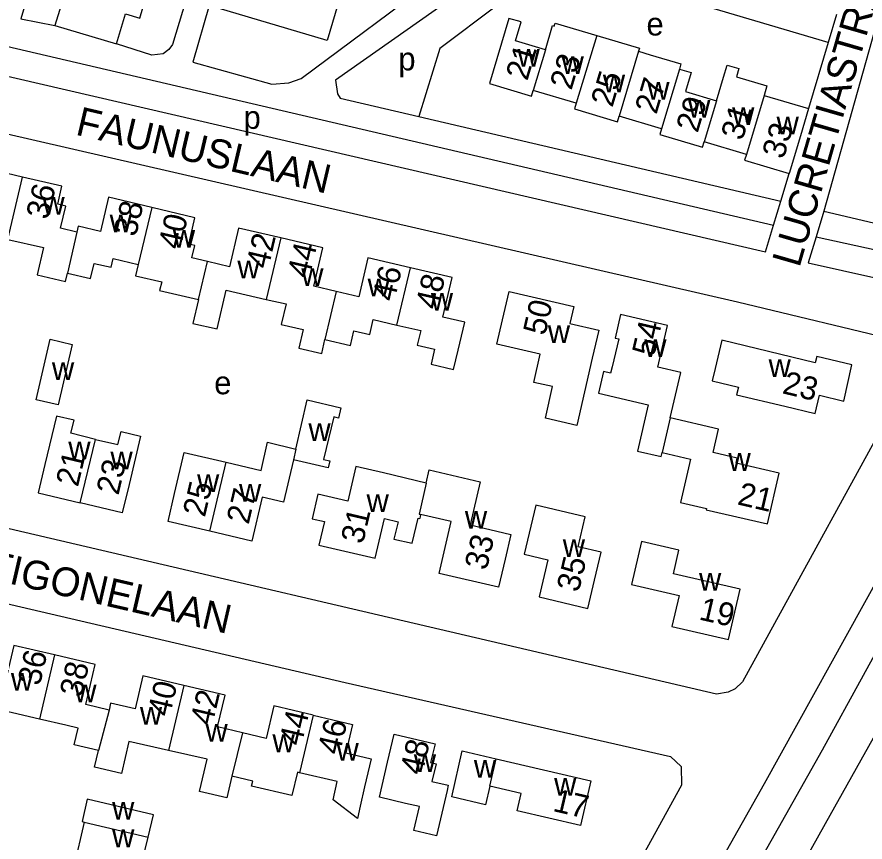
# Model space of a CAD drawing. Extents: x 161773 to 163836, y 384796 to 386521.
# Drawn here: x 162627.1 to 162774.3, y 385877.5 to 386020.7 of the extents above; entities that cross this region are included whole.
import ezdxf

# ---------------------------------------------------------------- set-up
doc = ezdxf.new("R2010")
doc.units = 0
for name, color, linetype in [('BLT_Basislijn', 7, 'Continuous'), ('BLT_Bebouwing', 7, 'Continuous'), ('BLT_Centroide', 7, 'Continuous'), ('BLT_Huisnummer', 7, 'Continuous'), ('BLT_Huisnummer_ tussenligend', 7, 'Continuous'), ('BLT_Onderverdeling_panden', 7, 'Continuous'), ('BLT_Straatnaam', 7, 'Continuous')]:
    doc.layers.add(name, color=color, linetype=linetype)

msp = doc.modelspace()

# ---------------------------------------------------------------- linework, layer by layer
at = {"layer": 'BLT_Basislijn'}
for p, q in [((162767.88, 386016.22), (162720.55, 386030.29)), ((162776.85, 386021.54), (162767.14, 385986.96)), ((162769.31, 386021.06), (162767.88, 386016.22)), ((162767.88, 386016.22), (162764.49, 386004.75)), ((162696.85, 386003.37), (162759.68, 385988.68)), ((162759.68, 385988.68), (162761.12, 385993.47)), ((162758.43, 385984.55), (162759.68, 385988.68)), ((162767.14, 385986.96), (162765.8, 385982.51)), ((162767.14, 385986.96), (162795.71, 385980.23)), ((162765.8, 385982.51), (162793.43, 385976.42))]:
    msp.add_line(p, q, dxfattribs=at)
for points in [[(162650.75, 386073.81), (162644.13, 386075.56), (162627.8, 386020.32), (162633.74, 386019.16)], [(162644.59, 385677.96), (162641.67, 385679.15), (162641.76, 385680.04), (162652.61, 385700), (162710.55, 385805.08), (162711.1, 385806.51), (162756.83, 385887.63), (162796.99, 385960.06), (162856.89, 386059.07)], [(162861.67, 386056.19), (162795.28, 385945.23), (162766.85, 385893.4), (162734.28, 385835.66), (162683.66, 385744.84), (162659.11, 385700), (162646.79, 385677.52), (162644.59, 385677.96)], [(162546.99, 386033.87), (162546.69, 386032.86), (162546.72, 386030.65), (162547.28, 386029.67), (162548.6, 386028.46), (162554.31, 386026.91), (162600, 386016.31), (162757.03, 385979.87), (162758.43, 385984.55)], [(162546.99, 386033.87), (162600, 386021.5), (162758.43, 385984.55)], [(162660.47, 386022.67), (162657.67, 386012.8), (162671.37, 386009.02), (162674.33, 386009.21), (162676.46, 386010), (162700.59, 386027.99), (162700.27, 386028.72), (162685.84, 386032.93)], [(162720.55, 386030.29), (162714.27, 386032.16), (162682.42, 386009.68), (162682.73, 386007.33), (162683.24, 386006.55), (162696.85, 386003.37)], [(162658.42, 386030.07), (162658.36, 386029.87), (162654.1, 386015.87), (162653.48, 386015.03), (162652.52, 386014.27), (162650.55, 386014.05), (162644.41, 386015.99)], [(162720.55, 386030.29), (162700.51, 386015.19), (162696.85, 386003.37)], [(162549.28, 386017.9), (162600, 386006.22), (162752.16, 385971.19), (162781.03, 385964.3), (162782.71, 385962.66), (162783.02, 385959.97), (162753.01, 385905.28), (162751.78, 385904.02), (162750.54, 385903.44), (162748.49, 385903.14), (162600, 385937.83), (162536.53, 385952.66)], [(162765.8, 385982.51), (162764.44, 385977.97), (162787.7, 385972.76), (162790.03, 385973), (162791.22, 385973.51), (162793.43, 385976.42)], [(162533.46, 385940.28), (162600, 385924.77), (162684.08, 385905.17), (162740.53, 385892.3), (162742.38, 385890.58), (162742.44, 385887.3), (162711.04, 385830.23)], [(162789.41, 385919.98), (162767.37, 385880.64), (162744.18, 385839.06)]]:
    msp.add_lwpolyline(points, dxfattribs=at)
at = {"layer": 'BLT_Bebouwing'}
for p, q in [((162633.74, 386019.16), (162644.41, 386015.99)), ((162724.18, 386005.67), (162716.72, 386007.91)), ((162738.99, 386001.24), (162731.62, 386003.43)), ((162753.7, 385996.8), (162746.37, 385998.99)), ((162660.19, 385978.21), (162657.49, 385978.85)), ((162697.17, 385934.32), (162697.04, 385933.6)), ((162702.57, 385885.3), (162704.41, 385893.27)), ((162704.41, 385893.27), (162710.27, 385891.91)), ((162709.17, 385887.16), (162708.42, 385883.94)), ((162708.42, 385883.94), (162702.57, 385885.3))]:
    msp.add_line(p, q, dxfattribs=at)
for points in [[(162640.37, 386028.88), (162639.27, 386025.15), (162638.75, 386023.41), (162635.31, 386024.43), (162633.74, 386019.16)], [(162644.41, 386015.99), (162645.96, 386021.2), (162648.44, 386020.46), (162649.52, 386024.08), (162652.32, 386023.25), (162652.89, 386025.16), (162650.08, 386026)], [(162682.81, 386022.83), (162680.95, 386016.57), (162660.47, 386022.67)], [(162718.82, 386014.94), (162713.63, 386016.49), (162714.62, 386019.79), (162712.51, 386020.42), (162709.14, 386009.11), (162716.43, 386006.93), (162716.72, 386007.91)], [(162718.82, 386014.94), (162720.08, 386019.16)], [(162720.08, 386019.16), (162720.37, 386019.07), (162720.52, 386019.57), (162727.73, 386017.44)], [(162727.73, 386017.44), (162735.14, 386015.22), (162734.99, 386014.71)], [(162734.99, 386014.71), (162737.03, 386014.1), (162742.35, 386012.51), (162742.08, 386011.6)], [(162742.08, 386011.6), (162744.11, 386011), (162743.12, 386007.7), (162748.49, 386006.09)], [(162748.49, 386006.09), (162749.73, 386010.23), (162750.35, 386012.31), (162752.4, 386011.69), (162751.99, 386010.29), (162757.26, 386008.71), (162756.77, 386007.05)], [(162756.77, 386007.05), (162764.49, 386004.75)], [(162724.18, 386005.67), (162723.89, 386004.7), (162731.33, 386002.47), (162731.62, 386003.43)], [(162764.49, 386004.75), (162763.07, 386000), (162761.12, 385993.47)], [(162738.99, 386001.24), (162738.7, 386000.26), (162746.09, 385998.05), (162746.37, 385998.99)], [(162753.7, 385996.8), (162753.4, 385995.78), (162761.12, 385993.47)], [(162628.08, 385992.88), (162621.26, 385994.45), (162620.57, 385991.44), (162619.09, 385991.79), (162618.22, 385988.06), (162614.98, 385988.81)], [(162637.55, 385983.33), (162634.71, 385983.99), (162635.6, 385987.82), (162634.23, 385988.14), (162634.95, 385991.29), (162628.08, 385992.88)], [(162650.52, 385987.58), (162643.02, 385989.36), (162641.65, 385983.45), (162637.78, 385984.35), (162637.55, 385983.33)], [(162657.49, 385978.85), (162658, 385981), (162656.95, 385981.25), (162657.29, 385982.72), (162658.02, 385985.8), (162650.52, 385987.58)], [(162672.9, 385982.31), (162665.59, 385984.03), (162664.01, 385977.31), (162660.19, 385978.21)], [(162625.58, 385982.05), (162631.72, 385980.63), (162630.63, 385975.92), (162635.59, 385974.77), (162635.92, 385976.19)], [(162682.53, 385973.01), (162678.64, 385973.92), (162680.21, 385980.6), (162672.9, 385982.31)], [(162635.92, 385976.19), (162639.92, 385975.27), (162640.52, 385977.89), (162643.5, 385977.21), (162643.85, 385978.72), (162648.18, 385977.72)], [(162695.4, 385977.11), (162688.02, 385978.84), (162686.43, 385972.09), (162682.53, 385973.01)], [(162648.18, 385977.72), (162647.73, 385975.72), (162652.26, 385974.68), (162651.87, 385973.19), (162658.65, 385971.61)], [(162693.08, 385967.18), (162697.19, 385966.22), (162696.6, 385963.69), (162699.6, 385962.98), (162698.99, 385960.39), (162702.91, 385959.47), (162703.69, 385962.8), (162704.83, 385967.67), (162701.02, 385968.56), (162702.63, 385975.42), (162695.4, 385977.11)], [(162658.65, 385971.61), (162657.68, 385967.46), (162661.87, 385966.53), (162663.44, 385973.23), (162670.39, 385971.63)], [(162726.96, 385961.42), (162724.3, 385949.78), (162718.83, 385951.04), (162720.08, 385956.5), (162716.82, 385957.24), (162717.94, 385962.12), (162710.43, 385963.84), (162711.41, 385968.12), (162712.52, 385972.99), (162723.76, 385970.42), (162723.08, 385967.44), (162728.08, 385966.29), (162726.96, 385961.42)], [(162670.39, 385971.63), (162673.83, 385970.84), (162673.01, 385967.29), (162676.81, 385966.41), (162676.07, 385963.17), (162680.01, 385962.24), (162680.58, 385964.65)], [(162740.47, 385951.07), (162742.3, 385958.94), (162738.35, 385959.86), (162740.04, 385967.13), (162731.87, 385969.03), (162730.91, 385964.93), (162731.55, 385964.78), (162730.4, 385959.92), (162730.14, 385958.81), (162728.9, 385959.1), (162728.02, 385955.37), (162736.68, 385953.34), (162734.82, 385945.3), (162738.92, 385944.35), (162739.08, 385945.07)], [(162680.58, 385964.65), (162684.99, 385963.61), (162685.6, 385966.2), (162688.35, 385965.55), (162688.96, 385968.15), (162693.08, 385967.18)], [(162632.9, 385964.72), (162636.71, 385963.83), (162634.27, 385953.33), (162630.45, 385954.21), (162632.9, 385964.72)], [(162766.37, 385955.01), (162770.6, 385953.96), (162772.01, 385960.27), (162765.91, 385961.72), (162765.65, 385960.65), (162749.46, 385964.54), (162748.27, 385959.63), (162747.76, 385957.49), (162752.32, 385956.39), (162752.01, 385955.09)], [(162752.01, 385955.09), (162760.4, 385953.08), (162765.64, 385951.82), (162766.37, 385955.01)], [(162675.53, 385945.67), (162677.48, 385954.19), (162683.36, 385952.8), (162682.95, 385951.05), (162682.1, 385951.26), (162680.35, 385943.86), (162681.45, 385943.6), (162681.16, 385942.38), (162675.1, 385943.82)], [(162640.74, 385947.35), (162636.5, 385948.4), (162637.04, 385950.66), (162633.98, 385951.39), (162631.97, 385942.96), (162630.81, 385938.09), (162638.12, 385936.35)], [(162739.08, 385945.07), (162744.01, 385943.93), (162742.26, 385936.4), (162746.79, 385935.34), (162746.74, 385935.14), (162750, 385934.38), (162757.37, 385932.67), (162759.41, 385941.46), (162751.9, 385943.2), (162752.11, 385944.11), (162747.94, 385945.08), (162748.88, 385949.11), (162740.47, 385951.07)], [(162640.74, 385947.35), (162644.67, 385946.44), (162645.21, 385948.71), (162648.59, 385947.9), (162646.59, 385939.51), (162645.42, 385934.61), (162638.12, 385936.35)], [(162663.43, 385943.37), (162669.49, 385941.95), (162670.64, 385946.83), (162675.53, 385945.67)], [(162660.63, 385931.4), (162653.35, 385933.1), (162654.48, 385937.97), (162656.14, 385945.07), (162663.43, 385943.37)], [(162675.1, 385943.82), (162673.41, 385936.44), (162669.7, 385937.31), (162667.92, 385929.69), (162660.63, 385931.4)], [(162698.15, 385939.77), (162690.74, 385941.51), (162685.93, 385942.64), (162684.53, 385936.64)], [(162698.15, 385939.77), (162698.69, 385942.07), (162707.52, 385940), (162705.76, 385932.5), (162712.83, 385930.85), (162711.82, 385926.54), (162710.68, 385921.68), (162700.38, 385924.09), (162702.48, 385933.07), (162697.17, 385934.32)], [(162684.53, 385936.64), (162679.35, 385937.85), (162678.35, 385933.57), (162680.48, 385933.07), (162679.53, 385929.01), (162689.28, 385926.72), (162690.9, 385933.61), (162693.27, 385933.06), (162692.56, 385930.05), (162695.71, 385929.31), (162696.73, 385933.67), (162697.04, 385933.6)], [(162726.21, 385918), (162727.37, 385922.89), (162728.53, 385927.76), (162724.52, 385928.72), (162725.75, 385933.89), (162717.18, 385935.93), (162716.31, 385932.29), (162715.15, 385927.43), (162719.28, 385926.45), (162717.75, 385920.02), (162726.21, 385918)], [(162741.04, 385924.01), (162741.98, 385928.09), (162735.49, 385929.59), (162733.76, 385922.15), (162742.04, 385920.24), (162740.79, 385914.86), (162750.62, 385912.58), (162752.64, 385921.32), (162741.04, 385924.01)], [(162633.65, 385909.93), (162626.58, 385911.57), (162624.93, 385904.45), (162620.34, 385905.52)], [(162643.12, 385900.37), (162639.09, 385901.3), (162640.71, 385908.29), (162633.65, 385909.93)], [(162656.11, 385904.64), (162648.96, 385906.32), (162647.67, 385900.55), (162643.39, 385901.54), (162643.12, 385900.37)], [(162666.26, 385896.41), (162661.95, 385897.43), (162663.25, 385902.95), (162656.11, 385904.64)], [(162678.53, 385899.45), (162671.69, 385901.07), (162670.37, 385895.44), (162666.26, 385896.41)], [(162631.07, 385898.79), (162626.36, 385899.88), (162624.08, 385900.41), (162623.11, 385895.95), (162618.4, 385897.04)], [(162678.53, 385899.45), (162685.37, 385897.84), (162684.21, 385892.94), (162688.57, 385891.91), (162687.42, 385887.05), (162686.67, 385883.68), (162686.2, 385881.56), (162681.98, 385884.76), (162682.72, 385887.97), (162676.18, 385889.47)], [(162641.26, 385893.34), (162637.08, 385894.3), (162637.78, 385897.23), (162635.6, 385897.74), (162631.07, 385898.79)], [(162701.98, 385887.33), (162701.76, 385886.38), (162701.54, 385885.42), (162699.92, 385878.51), (162695.99, 385879.43), (162696.97, 385883.61), (162694.58, 385884.17), (162690.02, 385885.24), (162691.44, 385891.3), (162692.58, 385896.17), (162699.68, 385894.51), (162698.92, 385891.25), (162699.85, 385891.04), (162699.14, 385887.99), (162701.98, 385887.33)], [(162653.44, 385893.32), (162646.58, 385894.88), (162645.29, 385889.34), (162640.58, 385890.43), (162641.26, 385893.34)], [(162664.42, 385888.86), (162663.56, 385885.11), (162658.84, 385886.2), (162660.13, 385891.81), (162653.44, 385893.32)], [(162710.27, 385891.91), (162726.73, 385888.09), (162724.93, 385880.34), (162713.94, 385882.89)], [(162676.18, 385889.47), (162675.8, 385889.56), (162674.86, 385885.52), (162667.86, 385887.13), (162668.06, 385888.02), (162664.42, 385888.86)], [(162713.94, 385882.89), (162714.63, 385885.89), (162709.17, 385887.16)], [(162649.9, 385878.32), (162650.82, 385882.19), (162639.35, 385884.88), (162638.44, 385881.01)], [(162638.83, 385880.92), (162637.03, 385873.14)], [(162638.44, 385881.01), (162638.83, 385880.92)], [(162637.03, 385873.14), (162640.96, 385872.21), (162641.62, 385874.99), (162648.72, 385873.32), (162649.9, 385878.32)]]:
    msp.add_lwpolyline(points, dxfattribs=at)
at = {"layer": 'BLT_Onderverdeling_panden'}
for p, q in [((162727.73, 386017.44), (162724.18, 386005.67)), ((162718.82, 386014.94), (162716.72, 386007.91)), ((162734.99, 386014.71), (162731.62, 386003.43)), ((162742.08, 386011.6), (162738.99, 386001.24)), ((162756.77, 386007.05), (162753.7, 385996.8)), ((162748.49, 386006.09), (162746.37, 385998.99)), ((162625.58, 385982.05), (162628.08, 385992.88)), ((162650.52, 385987.58), (162648.18, 385977.72)), ((162637.55, 385983.33), (162635.92, 385976.19)), ((162672.9, 385982.31), (162670.39, 385971.63)), ((162658.65, 385971.61), (162660.19, 385978.21)), ((162693.08, 385967.18), (162695.4, 385977.11)), ((162682.53, 385973.01), (162680.58, 385964.65)), ((162740.47, 385951.07), (162739.08, 385945.07)), ((162638.12, 385936.35), (162640.74, 385947.35)), ((162660.63, 385931.4), (162663.43, 385943.37)), ((162633.65, 385909.93), (162631.07, 385898.79)), ((162656.11, 385904.64), (162653.44, 385893.32)), ((162643.12, 385900.37), (162641.26, 385893.34)), ((162678.53, 385899.45), (162676.18, 385889.47)), ((162666.26, 385896.41), (162664.42, 385888.86)), ((162709.17, 385887.16), (162710.27, 385891.91)), ((162638.83, 385880.92), (162649.9, 385878.32))]:
    msp.add_line(p, q, dxfattribs=at)
for points in [[(162675.53, 385945.67), (162675.1, 385943.82)], [(162698.15, 385939.77), (162696.9, 385934.36), (162697.17, 385934.32)]]:
    msp.add_lwpolyline(points, dxfattribs=at)

# ---------------------------------------------------------------- texts
at = {"layer": 'BLT_Centroide'}
for s, p in [('e', (162736.37, 386017.44)), ('p', (162693.32, 386011.39)), ('w', (162713.98, 386012.02)), ('w', (162721.64, 386010.78)), ('w', (162728.8, 386007.58)), ('w', (162736.5, 386006.31)), ('w', (162743.59, 386003.19)), ('p', (162666.46, 386001.24)), ('w', (162751.23, 386001.91)), ('w', (162758.94, 386000.27)), ('w', (162631.56, 385986.36)), ('w', (162643.22, 385983.3)), ('w', (162654.19, 385980.61)), ('w', (162665.39, 385975.28)), ('w', (162676.47, 385973.98)), ('w', (162687.98, 385972.19)), ('w', (162698.95, 385969.7)), ('w', (162719.25, 385964.08)), ('w', (162735.98, 385961.64)), ('w', (162757.55, 385958.19)), ('w', (162633.21, 385957.62)), ('e', (162661.37, 385955.17)), ('w', (162677.71, 385947.08)), ('w', (162636.05, 385943.88)), ('w', (162643.36, 385942.12)), ('w', (162750.59, 385941.88)), ('w', (162658.39, 385938.23)), ('w', (162665.67, 385936.53)), ('w', (162687.8, 385934.72)), ('w', (162704.86, 385931.83)), ('w', (162721.84, 385926.92)), ('w', (162745.48, 385921.09)), ('w', (162626.08, 385903.75)), ('w', (162637.09, 385901.72)), ('w', (162648.47, 385897.84)), ('w', (162659.85, 385894.88)), ('w', (162671.47, 385893.05)), ('w', (162682.58, 385891.56)), ('w', (162696, 385889.61)), ('w', (162706.42, 385888.61)), ('w', (162720.34, 385885.5)), ('w', (162643.65, 385881.36)), ('w', (162643.65, 385876.56))]:
    msp.add_text(s, height=4, dxfattribs=at).set_placement(p)
at = {"layer": 'BLT_Huisnummer'}
for s, rotation, p in [('21', 73.3737, (162715.69, 386009.46)), ('25', 73.3744, (162730.45, 386004.84)), ('29', 73.3753, (162745.24, 386000.41)), ('33', 73.3765, (162760.16, 385995.85)), ('36', 76.8121, (162632.55, 385985.36)), ('38', 76.8129, (162647.78, 385982.39)), ('40', 76.8123, (162655.48, 385980.15)), ('42', 76.8276, (162670.74, 385976.79)), ('44', 76.8261, (162677.87, 385975.15)), ('46', 77.1007, (162692.63, 385971.12)), ('48', 77.1028, (162700.14, 385969.72)), ('50', 77.0979, (162718.79, 385965.24)), ('54', 76.9024, (162737.69, 385961.59)), ('23', 346.4924, (162759.77, 385955.37)), ('21', 76.5789, (162637.71, 385938.96)), ('23', 76.8448, (162644.74, 385937.53)), ('25', 76.8465, (162659.74, 385933.71)), ('27', 76.8448, (162667.33, 385932.46)), ('21', 346.9122, (162751.98, 385936.08)), ('31', 76.7984, (162687.17, 385929.05)), ('33', 76.7975, (162708.63, 385924.49)), ('35', 76.6022, (162724.6, 385920.67)), ('19', 346.9543, (162745.32, 385916.11)), ('36', 76.9408, (162631.1, 385904.44)), ('38', 77.4144, (162638.39, 385902.45)), ('40', 76.7386, (162653.64, 385899.06)), ('42', 76.7362, (162661.02, 385897.51)), ('44', 76.7403, (162676.47, 385893.99)), ('46', 76.7497, (162683.12, 385892.44)), ('48', 76.8445, (162697.44, 385888.95)), ('17', 346.9293, (162719.97, 385882.86))]:
    msp.add_text(s, height=4, rotation=rotation, dxfattribs=at).set_placement(p)
at = {"layer": 'BLT_Huisnummer_ tussenligend'}
for s, rotation, p in [('23', 73.3737, (162723.34, 386007.83)), ('27', 73.3744, (162738.09, 386003.63)), ('31', 73.3753, (162753.02, 385999.06))]:
    msp.add_text(s, height=4, rotation=rotation, dxfattribs=at).set_placement(p)
at = {"layer": 'BLT_Straatnaam'}
for s, rotation, p in [('LUCRETIASTRAAT', 73.8818, (162762.9, 385977.02)), ('FAUNUSLAAN', 346.7695, (162637.13, 386000.26)), ('ANTIGONELAAN', 347.0025, (162612.6, 385925.36))]:
    msp.add_text(s, height=5, rotation=rotation, dxfattribs=at).set_placement(p)

doc.saveas('drawing.dxf')
